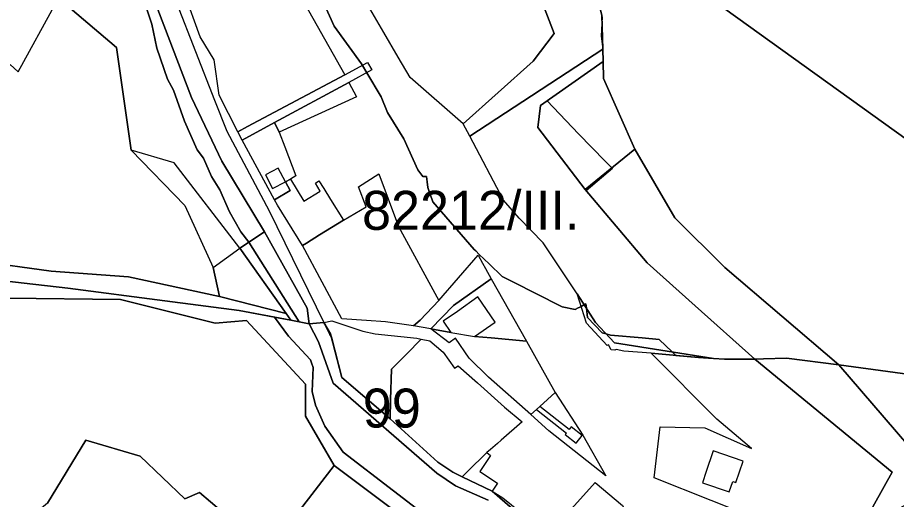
# Model space of a CAD drawing. Extents: x -477304 to -465429, y -1159113 to -1149210.
# Drawn here: x -474661.4 to -474323.2, y -1155110.9 to -1154925.4 of the extents above; entities that cross this region are included whole.
import ezdxf

# ---------------------------------------------------------------- set-up
doc = ezdxf.new("R2010")
doc.units = 0
for name, color, linetype in [('BPEJ_s', 7, 'Continuous'), ('orna_s', 7, 'Continuous'), ('PUPFL_s', 7, 'Continuous'), ('trav_porost_s', 7, 'Continuous'), ('voda_s', 7, 'Continuous'), ('zahrada_s', 7, 'Continuous')]:
    doc.layers.add(name, color=color, linetype=linetype)

msp = doc.modelspace()

# ---------------------------------------------------------------- linework, layer by layer
at = {"layer": 'BPEJ_s'}
for points in [[(-474612.84, -1154918.52), (-474609.65, -1154927.88), (-474607.74, -1154937.24), (-474603.7, -1154949.14), (-474601.36, -1154953.4), (-474597.11, -1154965.3), (-474592.22, -1154976.36), (-474589.88, -1154979.55), (-474586.69, -1154986.57), (-474583.5, -1154991.67), (-474579.88, -1155000.18), (-474575.46, -1155007.84), (-474572.42, -1155011.89), (-474552.98, -1155042.5), (-474556.27, -1155041.88), (-474562.53, -1155040.69), (-474576.08, -1155038.13), (-474604.69, -1155034.37), (-474642.09, -1155029.51), (-474675.76, -1155025.74)], [(-474460.08, -1155123.87), (-474478.75, -1155107.74), (-474490.34, -1155102.15), (-474493.9, -1155100.42), (-474499.6, -1155096.52), (-474518.05, -1155079.79), (-474536.62, -1155063.93), (-474540.54, -1155048.45), (-474541.18, -1155047.38), (-474543.05, -1155043.66), (-474543.58, -1155042.83), (-474549.14, -1155043.23), (-474552.98, -1155042.5), (-474572.42, -1155011.89), (-474575.46, -1155007.84), (-474579.88, -1155000.18), (-474583.5, -1154991.67), (-474586.69, -1154986.57), (-474589.88, -1154979.55), (-474592.22, -1154976.36), (-474597.11, -1154965.3), (-474601.36, -1154953.4), (-474603.7, -1154949.14), (-474607.74, -1154937.24), (-474609.65, -1154927.88), (-474612.84, -1154918.52)], [(-474543.74, -1154919.37), (-474539.48, -1154928.73), (-474529.06, -1154943.19), (-474528.7, -1154943.8), (-474527, -1154946.64), (-474521.41, -1154955.95), (-474519.07, -1154961.9), (-474512.69, -1154972.11), (-474507.37, -1154984.02), (-474505.46, -1154986.57), (-474503.97, -1154986.57), (-474503.76, -1154988.67), (-474503.55, -1154990.82), (-474501.57, -1154996.38), (-474485.68, -1155014.64), (-474485.08, -1155015.22), (-474483.69, -1155016.56), (-474479.87, -1155020.23), (-474474.84, -1155025.06), (-474468.97, -1155028.05), (-474463.18, -1155030.99), (-474462.2, -1155031.49), (-474451.87, -1155036.75), (-474446.77, -1155037.81), (-474445.71, -1155037.18), (-474445.26, -1155036.95), (-474444.49, -1155036.55), (-474443.81, -1155036.21), (-474443.31, -1155035.94), (-474442.66, -1155035.58)], [(-474436.47, -1154925.1), (-474436.78, -1154932.56), (-474436.19, -1154937.53), (-474436.08, -1154942.31), (-474457.55, -1154957.51), (-474445.5, -1154970.19), (-474435.29, -1154980.61), (-474432.73, -1154983.22), (-474432.58, -1154983.38), (-474432.48, -1154983.49), (-474442.54, -1154992.06), (-474419.12, -1155019.75), (-474400.61, -1155036.33), (-474377.69, -1155056.82), (-474384.79, -1155056.93), (-474389.36, -1155056.92), (-474393.53, -1155056.63), (-474399.31, -1155056.28), (-474408.08, -1155055.43), (-474409.44, -1155054.12), (-474414.45, -1155049.3), (-474421, -1155048.7), (-474433.16, -1155047.59), (-474434.91, -1155047.13), (-474436.35, -1155046.74), (-474442.09, -1155040.79), (-474442.48, -1155037.23), (-474442.66, -1155035.58), (-474443.31, -1155035.94), (-474443.81, -1155036.21), (-474444.49, -1155036.55), (-474445.26, -1155036.95), (-474445.71, -1155037.18), (-474446.77, -1155037.81), (-474451.87, -1155036.75), (-474462.2, -1155031.49), (-474463.18, -1155030.99), (-474468.97, -1155028.05), (-474474.84, -1155025.06), (-474479.87, -1155020.23), (-474483.69, -1155016.56), (-474485.08, -1155015.22), (-474485.68, -1155014.64), (-474501.57, -1154996.38), (-474503.55, -1154990.82), (-474503.76, -1154988.67), (-474503.97, -1154986.57), (-474505.46, -1154986.57), (-474507.37, -1154984.02), (-474512.69, -1154972.11), (-474519.07, -1154961.9), (-474521.41, -1154955.95), (-474527, -1154946.64), (-474528.7, -1154943.8), (-474529.06, -1154943.19), (-474539.48, -1154928.73), (-474543.74, -1154919.37)], [(-474436.47, -1154925.1), (-474436.78, -1154932.56), (-474436.19, -1154937.53), (-474436.08, -1154942.31), (-474457.55, -1154957.51)], [(-474457.55, -1154957.51), (-474445.5, -1154970.19), (-474435.29, -1154980.61), (-474432.73, -1154983.22), (-474432.58, -1154983.38), (-474432.48, -1154983.49), (-474442.54, -1154992.06), (-474419.12, -1155019.75), (-474400.61, -1155036.33), (-474377.69, -1155056.82), (-474324.85, -1155100.32), (-474338.44, -1155124.71)], [(-474768.45, -1155010.54), (-474759.51, -1155011.68), (-474724.26, -1155016.78), (-474721.33, -1155017.34), (-474716.21, -1155018.31), (-474707.73, -1155020.12), (-474704.07, -1155020.93), (-474698.91, -1155022.06), (-474675.76, -1155025.74), (-474642.09, -1155029.51), (-474604.69, -1155034.37), (-474576.08, -1155038.13), (-474562.53, -1155040.69), (-474557.13, -1155048.02), (-474548.63, -1155057.16), (-474548.23, -1155058.27), (-474547.56, -1155060.14), (-474547.99, -1155069.28), (-474546.71, -1155074.6), (-474543.1, -1155082.68), (-474536.08, -1155092.67), (-474497.38, -1155122.44)], [(-474442.66, -1155035.58), (-474442.48, -1155037.23), (-474442.09, -1155040.79), (-474436.35, -1155046.74), (-474434.91, -1155047.13), (-474433.16, -1155047.59), (-474421, -1155048.7), (-474414.45, -1155049.3), (-474409.44, -1155054.12), (-474408.08, -1155055.43), (-474399.31, -1155056.28), (-474393.53, -1155056.63), (-474389.36, -1155056.92), (-474384.79, -1155056.93), (-474377.69, -1155056.82), (-474324.85, -1155100.32), (-474338.44, -1155124.71)], [(-474497.38, -1155122.44), (-474536.08, -1155092.67), (-474543.1, -1155082.68), (-474546.71, -1155074.6), (-474547.99, -1155069.28), (-474547.56, -1155060.14), (-474548.23, -1155058.27), (-474548.63, -1155057.16), (-474557.13, -1155048.02), (-474562.53, -1155040.69), (-474556.27, -1155041.88), (-474552.98, -1155042.5), (-474549.14, -1155043.23), (-474543.58, -1155042.83), (-474543.05, -1155043.66), (-474541.18, -1155047.38), (-474540.54, -1155048.45), (-474536.62, -1155063.93), (-474518.05, -1155079.79), (-474499.6, -1155096.52), (-474493.9, -1155100.42), (-474490.34, -1155102.15), (-474478.75, -1155107.74), (-474460.08, -1155123.87)]]:
    msp.add_lwpolyline(points, dxfattribs=at)
at = {"layer": 'orna_s'}
msp.add_lwpolyline([(-474562.54, -1154965.79), (-474574.98, -1154972.58), (-474576.61, -1154969.37), (-474572.91, -1154967.39), (-474535.48, -1154947.42), (-474526.67, -1154942.72), (-474525.04, -1154945.58), (-474533.92, -1154950.37)], close=True, dxfattribs=at)
at = {"layer": 'PUPFL_s'}
for points in [[(-474401.02, -1154792.98), (-474389.88, -1154789.65), (-474368.88, -1154813.26), (-474288.93, -1154870.04), (-474151.26, -1154918.1), (-474196.87, -1155060.27), (-474423.82, -1154897.05), (-474437.12, -1154856.24), (-474466.83, -1154828.36), (-474472.89, -1154822.37), (-474492.08, -1154817.4), (-474493.19, -1154813.28), (-474484.24, -1154812.22), (-474454.76, -1154813.98), (-474442.51, -1154811.97), (-474419.5, -1154804.03)], [(-474436.48, -1154924.53), (-474444.82, -1154893.23), (-474456.47, -1154864.64), (-474477.92, -1154836.55), (-474484.7, -1154823.93), (-474492.08, -1154817.4), (-474472.89, -1154822.37), (-474466.83, -1154828.36), (-474437.12, -1154856.24), (-474423.82, -1154897.05), (-474196.87, -1155060.27), (-474201.31, -1155074.1), (-474255.55, -1155070.01), (-474304.79, -1155064.57), (-474345.32, -1155059.02), (-474389.27, -1155021.62), (-474408.45, -1155002.52), (-474423.87, -1154975.99), (-474435.93, -1154948.81), (-474436.08, -1154942.31), (-474436.19, -1154937.53)], [(-474454.86, -1154931.57), (-474467.62, -1154898.45), (-474444.82, -1154893.23), (-474436.48, -1154924.53), (-474436.19, -1154937.53), (-474487.36, -1154971.11), (-474489.87, -1154966.34), (-474462.95, -1154942.12)], [(-474436.08, -1154942.31), (-474435.93, -1154948.81), (-474423.87, -1154975.99), (-474442.96, -1154991.57), (-474461.19, -1154967.75), (-474460.09, -1154959.31)], [(-474419.12, -1155019.75), (-474442.96, -1154991.57), (-474423.87, -1154975.99), (-474408.45, -1155002.52), (-474389.27, -1155021.62), (-474345.32, -1155059.02), (-474365.44, -1155056.51), (-474374.39, -1155056.77), (-474377.69, -1155056.82), (-474400.61, -1155036.33)], [(-474556.27, -1155041.88), (-474558.01, -1155039.3), (-474575.89, -1155014.18), (-474566.37, -1155007.91), (-474549.95, -1155037.23), (-474549.14, -1155043.23)], [(-474558.01, -1155039.3), (-474583.66, -1155032.79), (-474586.14, -1155021.56), (-474575.89, -1155014.18)], [(-474335.72, -1155130.92), (-474338.44, -1155124.71), (-474324.85, -1155100.32), (-474377.69, -1155056.82), (-474374.39, -1155056.77), (-474365.44, -1155056.51), (-474345.32, -1155059.02), (-474305.77, -1155105.1), (-474329.76, -1155118.78)]]:
    msp.add_lwpolyline(points, close=True, dxfattribs=at)
for points in [[(-474499.48, -1155127.86), (-474539.48, -1155097.83), (-474550.54, -1155078.82), (-474550.52, -1155066.45), (-474573.32, -1155041.98), (-474585.39, -1155043.04), (-474621.8, -1155033.96), (-474664.95, -1155033.42), (-474675.76, -1155025.74), (-474642.09, -1155029.51), (-474604.69, -1155034.37), (-474576.08, -1155038.13), (-474556.27, -1155041.88), (-474549.14, -1155043.23), (-474545.55, -1155050.15), (-474539.9, -1155066.17), (-474500.04, -1155100.76), (-474492.82, -1155105.57), (-474480.23, -1155111.21)], [(-474261.06, -1155154.03), (-474305.77, -1155105.1), (-474345.32, -1155059.02), (-474304.79, -1155064.57), (-474255.55, -1155070.01), (-474201.31, -1155074.1), (-474187.41, -1155076.4), (-474150.59, -1155081.21), (-474138.62, -1155082.78), (-474100.94, -1155086.77), (-474083.93, -1155088.57), (-474056.26, -1155090.92), (-474051.68, -1155091.49), (-474013.91, -1155096.19), (-473985.74, -1155099.02), (-473906.92, -1155108.22), (-473903.83, -1155108.58), (-473873.33, -1155111.01)], [(-474649.82, -1155112.36), (-474635.13, -1155088.02), (-474614.26, -1155094.23), (-474597.01, -1155110.7), (-474591.41, -1155108.16), (-474574.47, -1155122.56)]]:
    msp.add_lwpolyline(points, dxfattribs=at)
at = {"layer": 'trav_porost_s'}
for points in [[(-474471.63, -1154875.43), (-474468.1, -1154875.48), (-474472.98, -1154879.42), (-474467.62, -1154898.45), (-474454.86, -1154931.57), (-474462.95, -1154942.12), (-474489.87, -1154966.34), (-474510.24, -1154948.53), (-474514.88, -1154940.67), (-474520.43, -1154931.09), (-474532.08, -1154910.96), (-474538.77, -1154900.7), (-474540.66, -1154897.76), (-474545.33, -1154890.58), (-474524.94, -1154891.7)], [(-474583.78, -1154955.28), (-474585.68, -1154941.61), (-474591.13, -1154932.86), (-474597.09, -1154916.02), (-474593.99, -1154914.66), (-474575.08, -1154906.29), (-474561.75, -1154900.72), (-474535.48, -1154947.42), (-474572.91, -1154967.39), (-474576.61, -1154969.37)], [(-474618.63, -1155025.23), (-474648.47, -1155023.04), (-474676.41, -1155019.2), (-474699.16, -1155020.03), (-474703.65, -1155014.86), (-474690.83, -1154994.46), (-474679.13, -1154969.99), (-474664.2, -1154943.5), (-474661.19, -1154946.26), (-474646.66, -1154919.8), (-474651.74, -1154913.48), (-474649.77, -1154908.73), (-474646.99, -1154916.71), (-474623.3, -1154936.98), (-474617.63, -1154976.46), (-474596.95, -1154997.68), (-474586.14, -1155021.56), (-474583.66, -1155032.79)], [(-474384.79, -1155056.93), (-474389.36, -1155056.92), (-474393.53, -1155056.63), (-474431.71, -1155050.6), (-474438.94, -1155042.76), (-474445.99, -1155031.75), (-474459.17, -1155012.09), (-474468.38, -1155002.64), (-474474.4, -1154995.69), (-474487.36, -1154971.11), (-474436.19, -1154937.53), (-474436.08, -1154942.31), (-474460.09, -1154959.31), (-474461.19, -1154967.75), (-474442.96, -1154991.57), (-474419.12, -1155019.75), (-474400.61, -1155036.33), (-474377.69, -1155056.82)], [(-474533.92, -1154950.37), (-474530.98, -1154955.93), (-474560.69, -1154969.55), (-474562.54, -1154965.79)], [(-474543.53, -1154991.24), (-474540.95, -1154995.37), (-474535.97, -1155003.34), (-474545.15, -1155009.07), (-474550.25, -1155012.18), (-474551.7, -1155013.07), (-474561.35, -1154997.58), (-474562.48, -1154995.51), (-474556.45, -1154992.01), (-474558.33, -1154988.6), (-474556.32, -1154987.59), (-474551.2, -1154996.08), (-474544.88, -1154992.23), (-474546.76, -1154989.09), (-474545.38, -1154988.22)], [(-474536.56, -1155041.38), (-474551.7, -1155013.07), (-474550.25, -1155012.18), (-474545.15, -1155009.07), (-474535.97, -1155003.34), (-474527.21, -1154998.23), (-474530.17, -1154990.52), (-474522.36, -1154985.55), (-474514.73, -1155005.8), (-474499.24, -1155034.33), (-474506.41, -1155041.89), (-474509.01, -1155044.08), (-474519.83, -1155042.48), (-474527.07, -1155042)], [(-474576.08, -1155038.13), (-474604.69, -1155034.37), (-474642.09, -1155029.51), (-474675.76, -1155025.74), (-474698.91, -1155022.06), (-474704.07, -1155020.93), (-474707.73, -1155020.12), (-474703.65, -1155014.86), (-474699.16, -1155020.03), (-474676.41, -1155019.2), (-474648.47, -1155023.04), (-474618.63, -1155025.23), (-474583.66, -1155032.79), (-474558.01, -1155039.3), (-474556.27, -1155041.88)], [(-474550.52, -1155066.45), (-474550.54, -1155078.82), (-474539.48, -1155097.83), (-474552.82, -1155115.18), (-474574.47, -1155122.56), (-474591.41, -1155108.16), (-474597.01, -1155110.7), (-474614.26, -1155094.23), (-474635.13, -1155088.02), (-474649.82, -1155112.36), (-474662.66, -1155122.9), (-474699.91, -1155140.43), (-474744.11, -1155102.65), (-474706.1, -1155048.54), (-474675.76, -1155025.74), (-474664.95, -1155033.42), (-474621.8, -1155033.96), (-474585.39, -1155043.04), (-474573.32, -1155041.98)], [(-474445.99, -1155031.75), (-474438.94, -1155042.76), (-474431.71, -1155050.6), (-474393.53, -1155056.63), (-474399.31, -1155056.28), (-474417.52, -1155054.51), (-474428.1, -1155053.75), (-474431.01, -1155053.19), (-474431.6, -1155053.44), (-474432.93, -1155053.32), (-474433.95, -1155051.31), (-474434.52, -1155051.64), (-474442.48, -1155042.98)], [(-474502.35, -1155045.2), (-474494.7, -1155046.56), (-474485.58, -1155048.18), (-474479.11, -1155048.73), (-474465.55, -1155049.89), (-474454.49, -1155069.69), (-474460.38, -1155075.07), (-474461.7, -1155076.23), (-474463.89, -1155078.13), (-474480.13, -1155063.79), (-474487.58, -1155056.46), (-474492.81, -1155048.82), (-474495.27, -1155050.59)], [(-474377.69, -1155056.82), (-474324.85, -1155100.32), (-474338.44, -1155124.71), (-474335.72, -1155130.92), (-474372.59, -1155119.94), (-474416.43, -1155102.54), (-474414.08, -1155082.92), (-474396.93, -1155083.31), (-474378.92, -1155091.32), (-474392.34, -1155079.97), (-474417.52, -1155054.51), (-474399.31, -1155056.28), (-474393.53, -1155056.63), (-474389.36, -1155056.92), (-474384.79, -1155056.93)], [(-474463.89, -1155078.13), (-474461.7, -1155076.23), (-474450.2, -1155085.36), (-474450.63, -1155085.91), (-474446.47, -1155089.21), (-474444.16, -1155086.27), (-474448.31, -1155082.96), (-474449.1, -1155083.99), (-474460.38, -1155075.07), (-474454.49, -1155069.69), (-474443.89, -1155086.15), (-474435.03, -1155101.76), (-474456.94, -1155084.51)], [(-474393.75, -1155092.22), (-474393.87, -1155092.59), (-474396.38, -1155100.11), (-474397.84, -1155104.51), (-474387.48, -1155107.96), (-474386.16, -1155104), (-474384.92, -1155104.41), (-474382.13, -1155096.09)], [(-474499.48, -1155127.86), (-474521.62, -1155125.68), (-474539.57, -1155124.05), (-474552.82, -1155115.18), (-474539.48, -1155097.83)]]:
    msp.add_lwpolyline(points, close=True, dxfattribs=at)
msp.add_lwpolyline([(-474615.77, -1154900.39), (-474594.44, -1154956.19), (-474582.74, -1154980.72), (-474566.37, -1155007.91), (-474575.89, -1155014.18), (-474601.17, -1154981.25), (-474617.63, -1154976.46), (-474623.3, -1154936.98), (-474646.99, -1154916.71)], dxfattribs=at)
at = {"layer": 'voda_s'}
for points in [[(-474600.23, -1154919.72), (-474585.53, -1154957.25), (-474580.79, -1154969.17), (-474564.55, -1154999.77), (-474543.58, -1155042.83), (-474549.14, -1155043.23), (-474549.95, -1155037.23), (-474566.37, -1155007.91), (-474582.74, -1154980.72), (-474594.44, -1154956.19), (-474615.77, -1154900.39)], [(-474480.23, -1155111.21), (-474492.82, -1155105.57), (-474500.04, -1155100.76), (-474539.9, -1155066.17), (-474545.55, -1155050.15), (-474549.14, -1155043.23), (-474543.58, -1155042.83), (-474540.89, -1155047.08), (-474536.62, -1155063.93), (-474518.05, -1155079.79), (-474499.6, -1155096.52), (-474493.9, -1155100.42), (-474490.34, -1155102.15), (-474478.75, -1155107.74), (-474474.68, -1155110.24), (-474461.3, -1155121.01)]]:
    msp.add_lwpolyline(points, dxfattribs=at)
at = {"layer": 'zahrada_s'}
for points in [[(-474574.98, -1154972.58), (-474562.54, -1154965.79), (-474560.69, -1154969.55), (-474558.53, -1154975.15), (-474554.32, -1154986.38), (-474556.32, -1154987.59), (-474558.33, -1154988.6), (-474561.06, -1154983.38), (-474565.97, -1154985.95), (-474563.24, -1154991.17), (-474558.33, -1154988.6), (-474556.45, -1154992.01), (-474562.48, -1154995.51)], [(-474502.35, -1155045.2), (-474509.01, -1155044.08), (-474506.41, -1155041.89), (-474499.24, -1155034.33), (-474484.11, -1155016.91), (-474482.5, -1155019.97), (-474481.35, -1155022.01), (-474479.1, -1155025.98), (-474493.66, -1155036.21)], [(-474465.55, -1155049.89), (-474479.11, -1155048.73), (-474485.58, -1155048.18), (-474477.56, -1155042.69), (-474484.29, -1155032.93), (-474492.1, -1155038.48), (-474497.63, -1155042.3), (-474494.7, -1155046.56), (-474502.35, -1155045.2), (-474493.66, -1155036.21), (-474479.1, -1155025.98)], [(-474540.89, -1155047.08), (-474543.58, -1155042.83), (-474540.39, -1155042.17), (-474528.52, -1155046.14), (-474523.72, -1155047.08), (-474507.78, -1155048.86), (-474506.07, -1155049.12), (-474511.69, -1155054.94), (-474513.1, -1155056.37), (-474517.48, -1155060.76), (-474517.83, -1155072.51), (-474518.05, -1155079.79), (-474536.62, -1155063.93)], [(-474499.6, -1155096.52), (-474518.05, -1155079.79), (-474517.83, -1155072.51), (-474517.48, -1155060.76), (-474513.1, -1155056.37), (-474511.69, -1155054.94), (-474506.07, -1155049.12), (-474502.7, -1155049.82), (-474497.58, -1155054.14), (-474493.25, -1155060.4), (-474491.81, -1155059.4), (-474484.37, -1155065.95), (-474473.96, -1155075.35), (-474467.22, -1155081.02), (-474475.22, -1155088.03), (-474476.74, -1155089.35), (-474477.56, -1155090.06), (-474479.4, -1155091.66), (-474480.77, -1155092.8), (-474488.25, -1155100.09), (-474490.34, -1155102.15), (-474493.9, -1155100.42)], [(-474479.34, -1155094), (-474483.49, -1155100.08), (-474476.66, -1155104.6), (-474478.75, -1155107.74), (-474490.34, -1155102.15), (-474488.25, -1155100.09), (-474480.77, -1155092.8)], [(-474439.75, -1155128.17), (-474450.51, -1155126.73), (-474452.03, -1155125.95), (-474444.64, -1155117.75), (-474448.21, -1155114.54), (-474439.08, -1155104.4), (-474428.61, -1155113.23), (-474424.29, -1155120.81), (-474422.25, -1155124.4), (-474431.27, -1155126.96)]]:
    msp.add_lwpolyline(points, close=True, dxfattribs=at)

# ---------------------------------------------------------------- texts
at = {"layer": 'BPEJ_s'}
for s, p in [('82212/III.', (-474528.82, -1155007.09)), ('99', (-474528.51, -1155083.2))]:
    msp.add_text(s, height=15, dxfattribs=at).set_placement(p)

doc.saveas('drawing.dxf')
